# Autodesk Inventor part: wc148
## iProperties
Shininess: 64.0
Length Units: 11272
Angle Units: 11279
Time Units: 11290
Mass Units: 11286
Length Display Precision: 3
Angle Display Precision: 2
Compacted: True
Part Number: wc148
Document SubType Name: Modeling
Created: 2004-08
Designer: John Blackburn
Manufacturer: Standard
Standards Organization: Custom
Density: 0.0
Volumn: 0.0
Area: 0.0
PropertySet Name: Model Information
Control State: 0
Master: False
Checked Out: False
Author: John Blackburn
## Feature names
1. Base1
